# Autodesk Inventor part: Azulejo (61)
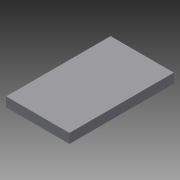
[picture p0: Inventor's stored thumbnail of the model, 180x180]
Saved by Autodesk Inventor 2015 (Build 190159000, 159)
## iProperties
Created: 2015-04
Part Number: Azulejo (61)
Material: Genérico
Document SubType Name: Modeling
Designer: Felipe
Density: 1 g/cm^3
Appearance: Padrão
Author: Felipe
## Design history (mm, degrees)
sketch "Sketch1"
  geometry: L1 (5561.362, 748.164)-(5161.362, 748.164); L2 (4081.362, 848.164)-(2601.362, 848.164); L3 (2581.362, 848.164)-(1101.362, 848.164); L4 (7101.362, 848.164)-(7101.362, 908.164); L5 (5601.362, 908.164)-(7081.362, 908.164); L6 (4101.362, 748.164)-(4101.362, 808.164); L7 (2601.362, 848.164)-(2601.362, 908.164); L8 (2601.362, 908.164)-(4081.362, 908.164); L9 (4081.362, 908.164)-(4081.362, 848.164); L10 (7081.362, 908.164)-(7081.362, 848.164); L11 (1101.362, 848.164)-(1101.362, 908.164); L12 (1101.362, 908.164)-(2581.362, 908.164); L13 (2581.362, 908.164)-(2581.362, 848.164); L14 (1081.362, 908.164)-(1081.362, 828.268); L15 (115.504, 828.363)-(115.504, 88.164); L16 (125.504, 828.363)-(125.504, 88.164); L17 (1081.362, 88.164)-(1081.362, 888.164); L18 (7101.362, 888.164)-(7101.362, 848.164); L19 (5601.362, 908.164)-(7081.362, 908.164); L20 (7081.362, 888.164)-(7081.362, 848.164); L21 (5561.362, 88.164)-(5561.362, 748.164); L22 (4101.362, 808.164)-(5101.362, 808.164); L23 (4101.362, 748.164)-(4101.362, 788.164); L24 (4081.362, 848.164)-(4081.362, 888.164); L25 (4081.362, 908.164)-(2601.362, 908.164); L26 (2601.362, 888.164)-(2601.362, 88.164); L27 (2581.362, 88.164)-(2581.362, 888.164); L28 (2581.362, 908.164)-(1101.362, 908.164); L29 (1101.362, 888.164)-(1101.362, 88.164); L30 (1081.362, 908.164)-(681.362, 908.164); L31 (581.362, 88.164)-(581.362, 68.164); L32 (581.362, 68.164)-(1081.362, 68.164); L33 (1601.362, 88.164)-(1601.362, 68.164); L34 (1601.362, 68.164)-(1101.362, 68.164); L35 (3601.362, 88.164)-(3601.362, 68.164); L36 (3601.362, 68.164)-(2601.362, 68.164); L37 (5161.362, -11.836)-(5161.362, 748.164); L38 (5161.362, 748.164)-(5561.362, 748.164); L39 (5561.362, 748.164)-(5561.362, 88.164); L40 (5561.362, 88.164)-(5161.362, 88.164); L41 (5161.362, 88.164)-(5161.362, 748.164); L42 (1081.362, 68.164)-(125.504, 68.164); L43 (125.504, 68.164)-(125.504, 908.164); L44 (125.504, 908.164)-(1081.362, 908.164); L45 (1081.362, 908.164)-(1081.362, 68.164); L46 (5161.362, 748.164)-(5161.362, 88.164); 3 further points
  constraints: 92 end point, 13 point on line, 4 parallel, 2 horizontal, 2 perpendicular
  dimensions: "d2" = 88.16406 distance from line of L40 point (0, 0); "d3" = 660 distance between parallel lines of L40 L1; "d4" = 400 distance between parallel lines of L21 L41; "d5" = 5161.36173 distance from line of point (0, 0) L41
extrude "Extrusion1" new body sketch "Sketch1" distance "d0" = 60; taper "d1" = 0 deg
body "Solid1"
